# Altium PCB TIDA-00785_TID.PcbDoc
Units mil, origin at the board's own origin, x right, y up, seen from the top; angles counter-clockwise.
Board outline 1501 x 1000 mil, 2 copper layers (Top Layer, Bottom Layer), stack 62 mil thick; 48 components, 15 nets, 95 pads, 18 vias.
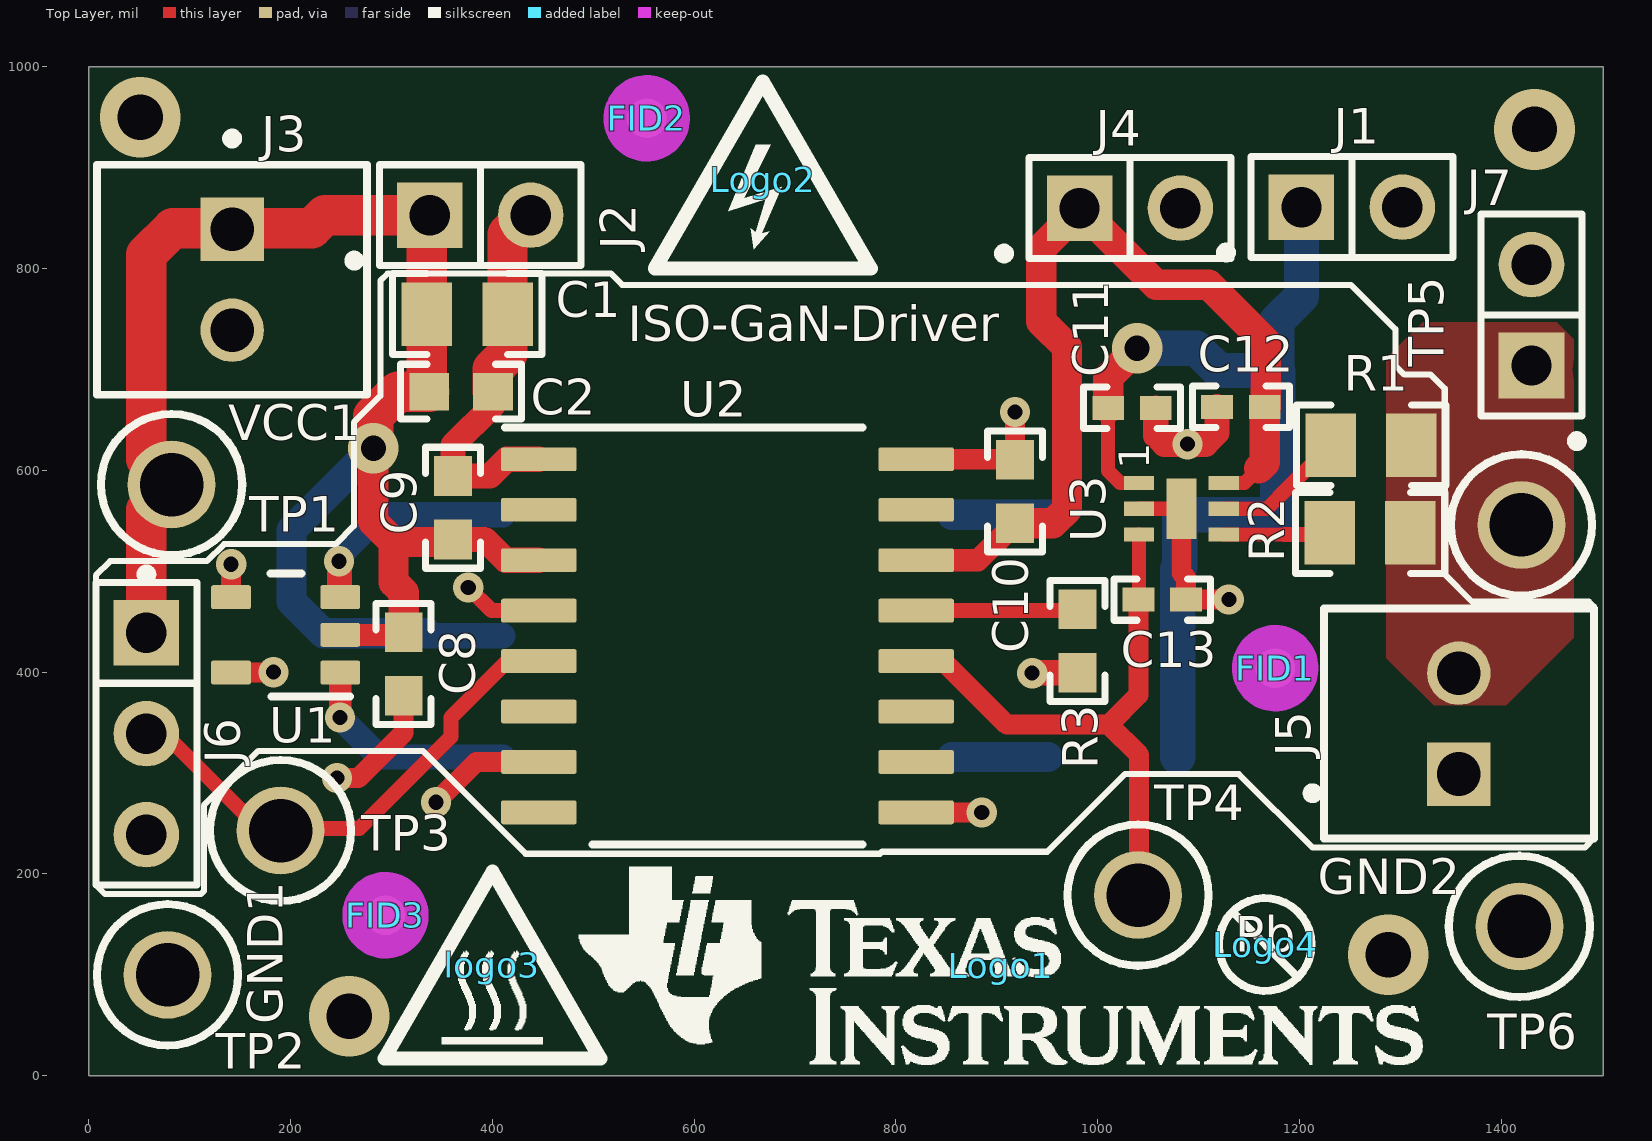
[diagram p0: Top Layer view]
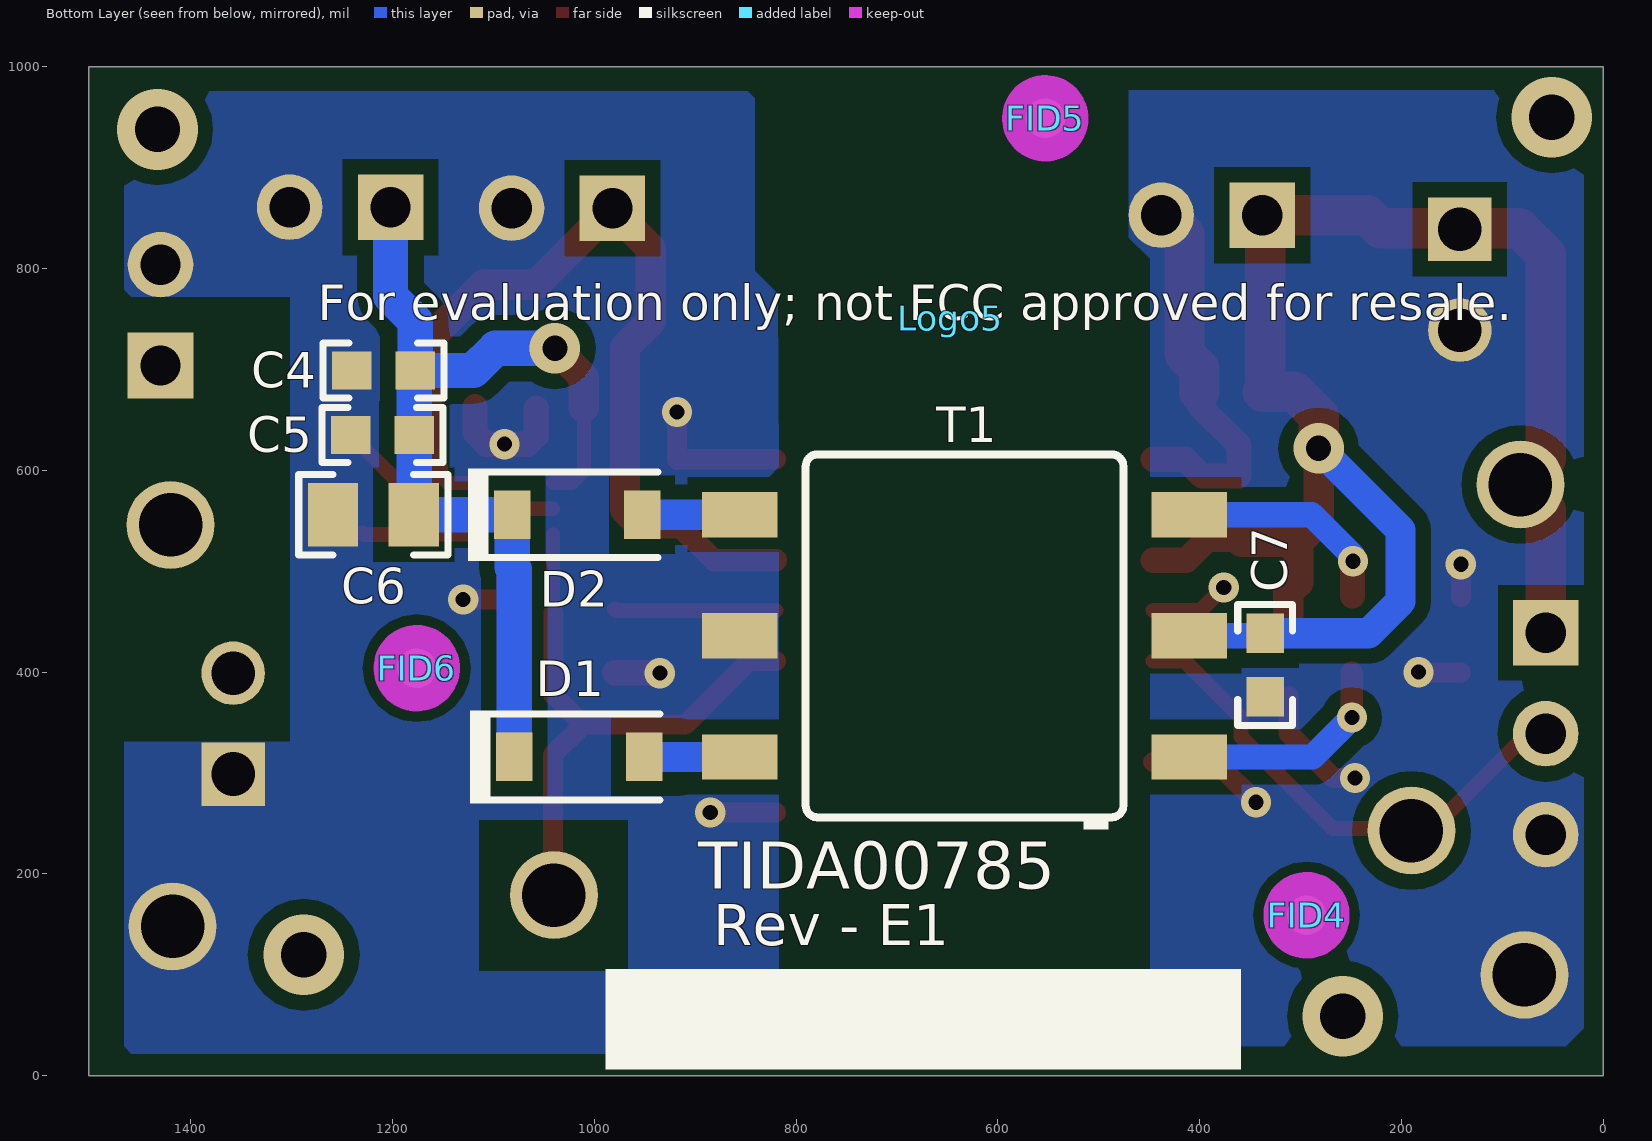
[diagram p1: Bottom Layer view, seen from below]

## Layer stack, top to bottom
Top Solder: solder mask 0.4, Solder Resist, Dk 3.5
Top Layer: signal copper 1.4
Dielectric1: core 59.2, FR-4, Dk 4.8
Bottom Layer: signal copper 1.4
Bottom Solder: solder mask 0.4, Solder Resist, Dk 3.5

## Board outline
0,0 0,1000 1501,1000 1501,0

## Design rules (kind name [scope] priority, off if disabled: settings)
AcuteAngle [All] p1: minimum=4.50000000000000E+0001 checktracksonly=FALSE
AssemblyTestPointUsage [All] p1: valid=2
Clearance Clearance_1 [All] p1: gap=10 except(8: Track-SMDPad; 9.4: SMDPad-SMDPad Track-Track; 15: Poly-Poly SMDPad-Poly Poly-Region Track-Poly Via-Poly THPad-Poly)
Clearance Clearance_Keepouts [((IsTrack Or IsArc) And Not InPoly) And IsFree and IsKeepOut vs ((IsTrack Or IsArc) And Not InPoly) And IsFree and IsKeepOut] p2: gap=0
Clearance Clearance_BoardEdge_MountingHoles [OnCopper and InComponentClass('Mounting Holes') vs IsKeepOut] p3: gap=40
Clearance Clearance_BoardEdge_Poly [OnCopper and InPoly vs IsKeepOut] p4: gap=25
Clearance Clearance_BoardEdge [OnCopper and Not InComponentClass('Logo') and not InComponentClass('FiducialMark') and not InRegion(1000,500,4000,800) and Not IsKeepout vs IsKeepOut] p5: gap=20
Clearance Clearance_Poly [All] p6: gap=100
Clearance [All] p7: gap=7.87
ComponentClearance ComponentClearance_MountingHoles_FiducialMarks [InComponentClass('Mounting Holes') vs InComponentClass('FiducialMark')] p1: gap=18 collisioncheckmode=3 verticalgap=10 showdistances=FALSE
ComponentClearance ComponentClearance_Shunt [InComponentClass('Header') vs InComponentClass('Shunt')] p2: gap=0 collisioncheckmode=3 verticalgap=0 showdistances=FALSE
ComponentClearance ComponentClearance_Logo [InComponentClass('Logo')] p3: gap=18 collisioncheckmode=3 verticalgap=10 showdistances=FALSE
ComponentClearance ComponentClearance_ScrewToNut [(HasFootprint('NY PMS 440 0025 PH')) vs (HasFootprint('Keystone_1902C'))] p4: gap=5 collisioncheckmode=3 verticalgap=10 showdistances=FALSE
ComponentClearance ComponentClearance_MountingHoles [InComponentClass('Mounting Holes')] p5: gap=18 collisioncheckmode=3 verticalgap=100000 showdistances=FALSE
ComponentClearance ComponentClearance_SmallPassives [HasFootprint('0201*') or HasFootprint('0402*') or HasFootprint('0508') or HasFootprint('0603*') or HasFootprint('0612') or HasFootprint('0805*') or HasFootprint('0815*') or HasFootprint('0830*') or HasFootprint('1206*') or HasFootprint('1210*') or HasFootprint('1808*') or HasFootprint('1812*') or HasFootprint('1825*') or HasFootprint('2010*') or HasFootprint('2220*') or HasFootprint('2225*') or HasFootprint('2512*') or HasFootprint('2728*') or HasFootprint('3518*') vs HasFootprint('0201*') or HasFootprint('0402*') or HasFootprint('0508') or HasFootprint('0603*') or HasFootprint('0612') or HasFootprint('0805*') or HasFootprint('0815*') or HasFootprint('0830*') or HasFootprint('1206*') or HasFootprint('1210*') or HasFootprint('1808*') or HasFootprint('1812*') or HasFootprint('1825*') or HasFootprint('2010*') or HasFootprint('2220*') or HasFootprint('2225*') or HasFootprint('2512*') or HasFootprint('2728*') or HasFootprint('3518*')] p6: gap=18 collisioncheckmode=3 verticalgap=10 showdistances=FALSE
ComponentClearance ComponentClearance_THtoSMT [IsThruComponent vs IsSMTComponent] p7: gap=18 collisioncheckmode=3 verticalgap=18 showdistances=FALSE
ComponentClearance ComponentClearance_THtoTH [IsThruComponent vs IsThruComponent] p8: gap=18 collisioncheckmode=3 verticalgap=18 showdistances=FALSE
ComponentClearance [All] p9: gap=16 collisioncheckmode=3 verticalgap=10 showdistances=FALSE
DiffPairsRouting [All] p1: maxlimit=100 minlimit=10 mostfreqgap=10 toplayer_minwidth=15 toplayer_maxwidth=15 toplayer_prefwidth=15 bottomlayer_minwidth=15 bottomlayer_maxwidth=15 bottomlayer_prefwidth=15 maxuncoupledlength=1000
FabricationTestPointUsage TestPointUsage [All] p1: valid=2 allowmultiple=FALSE
FabricationTestpoint Testpoint [All] p1: side=3 testpointundercomponent=TRUE minsize=40 maxsize=100 preferedsize=60 minholesize=0 maxholesize=40 preferedholesize=32 testpointgrid=1 allowsidetop=TRUE allowsidebottom=TRUE usegrid=TRUE gridtolerance=0.01
FanoutControl Fanout_LCC [IsLCC] p1: bgadir=Out bgaviamode=Centered fanoutstyle=Auto fanoutdirection=Alternating viagrid=1 // Fanout_LCC (Default Rule)
FanoutControl Fanout_BGA [IsBGA] p2: bgadir=Out bgaviamode=Centered fanoutstyle=Auto fanoutdirection=Alternating viagrid=1 // Fanout_BGA (Default Rule)
FanoutControl Fanout_Default [All] p4: bgadir=Out bgaviamode=Centered fanoutstyle=Auto fanoutdirection=Alternating viagrid=1 // Fanout_Default (Default Rule)
FanoutControl Fanout_Small [(CompPinCount < 5)] p5: bgadir=Out bgaviamode=Centered fanoutstyle=Auto fanoutdirection=OutThenIn viagrid=1 // Fanout_Small (Default Rule)
HoleSize [All] p1: absolutevalues=TRUE maxlimit=251 minlimit=8 maxpercent=80.000 minpercent=20.000
MinimumAnnularRing MinimumAnnularRing_ThermalPadVias [IsVia and InAnyComponent] p1: minimumring=5.91
MinimumAnnularRing [All] p2: minimumring=9
MinimumSolderMaskSliver MinimumSolderMaskSliver_Logo [InComponentClass('Logo') vs InComponentClass('Logo')] p1: minsoldermaskwidth=0.7
MinimumSolderMaskSliver [All] p2: minsoldermaskwidth=3.94
PlaneClearance [All] p1: clearance=50
PlaneConnect [All] p1: planeconnectstyle=Direct reliefexpansion=10 reliefentries=4 reliefconductorwidth=10 reliefairgap=10
PolygonConnect [All] p1: connectstyle=Direct reliefconductorwidth=10 reliefentries=4 polygonreliefangle="90 Angle" airgapwidth=10
RoutingVias ThermalPadVias [IsVia and InAnyComponent] p1: holewidth=7.87 width=19.68 viastyle="Through Hole" minholewidth=7.87 minwidth=19.68 maxholewidth=12.99 maxwidth=23.62
RoutingVias [All] p2: holewidth=16 width=34 viastyle="Through Hole" minholewidth=7.87 minwidth=26 maxholewidth=40 maxwidth=65
SilkToSilkClearance SilkToSilkClearance_Pb-FreeLogo [(HasFootprint('Pb-Free_Overlay_Medium') OR HasFootprint('Pb-Free_Overlay_Small')) vs (HasFootprint('Pb-Free_Overlay_Medium') OR HasFootprint('Pb-Free_Overlay_Small'))] p1: silktosilkclearance=0
SilkToSilkClearance [All] p2: silktosilkclearance=4
SilkToSolderMaskClearance "Silk to Solder Mask Opening" [IsPad] p1: minsilkscreentomaskgap=4 clearancetoexposedcopper=TRUE
SolderMaskExpansion [All] p1: expansion=1.97
UnpouredPolygon [All] p1: allowunpoured=FALSE
Width [All] p1: maxlimit=100 minlimit=6 preferedwidth=10 checkconnectedcopper=TRUE
14 further rules are at their usual default settings.

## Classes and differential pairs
component class TIDA-00785_RefD-ISO-GaN-Driver: C1 C2 C4 C5 C6 C7 C8 C9 C10 C11 C12 C13 D1 D2 J1 J2 J3 J4 J5 J6 J7 R1 R2 R3 T1 TP1 TP2 TP3 TP4 TP5 TP6 U1 U2 U3
component class Logo: Logo1
component class TIDA-00785_TID_Hardware: FID1 FID2 FID3 FID4 FID5 FID6 Logo1 Logo2 logo3 Logo4 Logo5 ZZ1 ZZ2 ZZ3
component class FiducialMark: FID1 FID2 FID3 FID4 FID5 FID6
component class AssemblyNote: ZZ1 ZZ2 ZZ3
component class Header: J1 J2 J4 J6 J7

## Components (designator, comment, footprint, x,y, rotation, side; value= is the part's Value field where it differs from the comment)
C1 "GRM21BR6YA106KE43L" 0805_HV 375,755 r0 top
C2 "GRM188R61H105KAALD" 0603 369,678 r0 top
C4 "06033C104JAT2A" 0603 1209,699 r0 bottom
C5 "GRM188R61H105KAALD" 0603 1210,635 r0 bottom
C6 "GRM21BR6YA106KE43L" 0805_HV 1219,556 r0 bottom
C7 "06033C104JAT2A" 0603 335,407 r270 bottom
C8 "GRM188R61H105KAALD" 0603 312,408 r270 top
C9 "06033C104JAT2A" 0603 361,563 r90 top
C10 "GRM188R61E105KA12D" 0603 918,579 r90 top
C11 "C1005X7R1C224K050BC" 0402 1034,662 r0 top
C12 "C1005X7R1C224K050BC" 0402 1142,663 r180 top
C13 "C0402C101J3GACTU" 0402 1064,472 r0 top
D1 "MBR0520LT1G" SOD-123 1015,316 r180 bottom
D2 "MBR0520LT1G" SOD-123 1017,556 r180 bottom
FID1 "Fiducial" Fiducial10-20 1176,404 r0 top
FID2 "Fiducial" Fiducial10-20 553,949 r0 top
FID3 "Fiducial" Fiducial10-20 294,159 r0 top
FID4 "Fiducial" Fiducial10-20 294,159 r180 bottom
FID5 "Fiducial" Fiducial10-20 553,949 r180 bottom
FID6 "Fiducial" Fiducial10-20 1176,404 r180 bottom
J1 "HTSW-102-07-G-S" Samtec_HTSW-102-07-G-S 1252,861 r0 top
J2 "HTSW-102-07-G-S" Samtec_HTSW-102-07-G-S 388,853 r0 top
J3 "282834-2" TEC_282834-2 142,789 r270 top
J4 "HTSW-102-07-G-S" Samtec_HTSW-102-07-G-S 1032,860 r0 top
J5 "282834-2" TEC_282834-2 1358,349 r90 top
J6 "HTSW-103-07-G-S" Samtec_HTSW-103-07-G-S 57,339 r270 top
J7 "HTSW-102-07-G-S" Samtec_HTSW-102-07-G-S 1430,754 r90 top
Logo1 "Texas Instruments" TI_Stacked_Overlay_Small 904,109 r0 top
Logo2 "DANGER HIGH VOLTAGE" IEC_HighVoltage_Small 668,888 r0 top
logo3 "CAUTION HOT SURFACE" IEC_HotSurface_Small 400,110 r0 top
Logo4 "Pb-Free Symbol" Pb-Free_Overlay_Small 1166,130 r0 top (schematic designator Logo2)
Logo5 "FCC disclaimer" FCC_disclaimer 647,751 r180 bottom
R1 "CRCW080510R0FKEA" 0805_HV 1271,625 r0 top
R2 "CRCW08051R00FKEA" 0805_HV 1270,538 r0 top
R3 "CRCW06030000Z0EA" 0603 980,431 r90 top
T1 "750313638" Wurth_750313638 633,436 r0 bottom
TP1 "5005" Keystone5005 82,586 r180 top
TP2 "5006" Keystone5006 78,100 r0 top
TP3 "5122" Keystone5122#1 197,243 r90 top
TP4 "5122" Keystone5122#2 1040,179 r90 top
TP5 "5122" Keystone5122#2 1420,546 r90 top
TP6 "5006" Keystone5006 1418,148 r90 top
U1 "SN6501DBVR" DBV0005A_N 195,437 r180 top
U2 "ISO7821FDWR" DW0016B_N 633,436 r0 top
U3 "UCC27611DRV" DRV 1083,562 r270 top
ZZ1 "These assemblies are ESD sensitive, ESD precautions shall be observed." AssemblyNote -14,3586.11 r0 top
ZZ2 "These assemblies must be clean and free from flux and all contaminants. Use of no clean flux is not acceptable." AssemblyNote -14,3497.56 r0 top
ZZ3 "These assemblies must comply with workmanship standards IPC-A-610 Class 2, unless otherwise specified." AssemblyNote -14,3409 r0 top

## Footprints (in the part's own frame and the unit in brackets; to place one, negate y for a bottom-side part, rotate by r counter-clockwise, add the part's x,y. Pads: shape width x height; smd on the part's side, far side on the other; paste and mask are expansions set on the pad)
0402 [mm] "0402 from SM-752 data"
  rect 0.8x0.6 smd: 1(-0.6,0) 2(0.6,0)
  silkscreen extent -1.22,-0.52 1.22,0.52, body extent -0.55,-0.3 0.55,0.3, height 0.6
0603 [mm] "0603 from SM-752 data"
  rect 1x0.95 smd: 1(-0.8,0) 2(0.8,0)
  silkscreen extent -1.52,-0.69 1.52,0.69, body extent -0.87,-0.47 0.87,0.47, height 1
0805_HV [mil] "0805 with 30mil clearance between pads"
  rect 50x63 smd: 1(-40,0) 2(40,0)
  silkscreen extent -74,-40 74,40, body extent -43,-29 43,29, height 57
AssemblyNote [mil] "Assembly Note"
DBV0005A_N [mm] "SOT23, 5-Leads, Body 2.9x1.6mm, Pitch 0.95mm, Lead Span 2.8mm, IPC Medium Density"
  rrect17% 1x0.6 smd: 1(-1.375,0.95) 2(-1.375,0) 3(-1.375,-0.95) 4(1.375,-0.95) 5(1.375,0.95)
  silkscreen extent -1.63,-1.55 0.38,1.55, body extent -1.42,-1.46 1.42,1.46, height 1.09
DRV [mil]
  rect 14x30 smd mask+1.18: 1(-25.6,-42) 2(0,-42) 3(25.6,-42) 4(25.6,42) 5(0,42) 6(-25.6,42)
  rect 60x30 smd mask+1.15: 7(0,0)
DW0016B_N [mm] "SOIC, 16-Leads, Body 10.5x7.6mm, Pitch 1.27mm, IPC Medium Density"
  rrect17% 1.9x0.6 smd: 1(-4.75,4.445) 2(-4.75,3.175) 3(-4.75,1.905) 4(-4.75,0.635) 5(-4.75,-0.635) 6(-4.75,-1.905) 7(-4.75,-3.175) 8(-4.75,-4.445) 9(4.75,-4.445) 10(4.75,-3.175) 11(4.75,-1.905) 12(4.75,-0.635) 13(4.75,0.635) 14(4.75,1.905) 15(4.75,3.175) 16(4.75,4.445)
  silkscreen extent -5.6,-5.25 3.4,5.25, body extent -5.17,-5.15 5.17,5.15, height 2.59
FCC_disclaimer [mil]
Fiducial10-20 [mm]
  round 1 smd mask+0.5: 1(0,0)
  Top Layer keep-out circle w1.178: c0,0 r0.5
IEC_HighVoltage_Small [mil]
  silkscreen extent -107,-88 107,97
IEC_HotSurface_Small [mil]
  silkscreen extent -107,-93 107,92
Keystone5005 [mil] "Keystone Compact loops"
  round 87 hole 63: 1(0,0)
  silkscreen extent -70,-70 70,70, body extent -63,-63 62,63, height 225
Keystone5006 [mil] "Keystone Compact loops"
  round 87 hole 63: 1(0,0)
  silkscreen extent -70,-70 70,70, body extent -63,-63 62,63, height 225
Keystone5122#1 [mil] "Keystone Compact loops"
  round 87 hole 63: 1(0,7)
  silkscreen extent -70,-63 70,77, body extent -63,-56 62,70, height 225
Keystone5122#2 [mil] "Keystone Compact loops"
  round 87 hole 63: 1(0,0)
  silkscreen extent -70,-70 70,70, body extent -63,-63 62,63, height 225
Pb-Free_Overlay_Small [mil]
  silkscreen extent -46,-46 46,46
Samtec_HTSW-102-07-G-S [mm] "Samtec 100mil, 1x2, 230 mil above insulator"
  rect 1.65x1.65 hole 1.016 mask+0: 1(-1.27,0)
  round 1.65 hole 1.016 mask+0: 2(1.27,0)
  silkscreen extent -3.3,-1.27 2.54,1.27, body extent -2.54,-1.27 2.54,1.27, height 8.38
Samtec_HTSW-103-07-G-S [mm] "Samtec 100mil, 1x3, 230 mil above insulator"
  rect 1.65x1.65 hole 1.016 mask+0: 1(-2.54,0)
  round 1.65 hole 1.016 mask+0: 2(0,0) 3(2.54,0)
  silkscreen extent -4.14,-1.27 3.81,1.27, body extent -3.81,-1.27 3.81,1.27, height 8.38
SOD-123 [mm] "On Semi recommended land pattern"
  rect 0.915x1.22 smd: 1(-1.637,0) 2(1.637,0)
  silkscreen extent -2.74,-1.17 2.03,1.17, body extent -1.93,-0.9 1.93,0.9, height 1.35
TEC_282834-2 [mm] "TEC"
  rect 1.6x1.6 hole 1.1: 1(-1.27,0)
  round 1.6 hole 1.1: 2(1.27,0)
  silkscreen extent -3.66,-3.4 2.9,3.4, body extent -2.77,-3.25 2.77,3.25, height 10.01
TI_Stacked_Overlay_Small [mil]
  silkscreen extent -418,-98 418,98
Wurth_750313638 [mm] "SMD, 6-Leads, Body 8x9.14mm, Pitch 3.05mm"
  rect 1.9x1.14 smd: 1(-5.655,3.05) 2(-5.655,0) 3(-5.655,-3.05) 4(5.655,-3.05) 5(5.655,0) 6(5.655,3.05)
  silkscreen extent -4,-4.57 4,4.87, body extent -6.35,-4.57 6.35,4.57, height 7.62

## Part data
C1 C6: "CAP, CERM, 10 µF, 35 V, +/- 10%, X5R, 0805"
C2 C5 C8: "CAP, CERM, 1 µF, 50 V, +/- 10%, X5R, 0603"
C4 C7 C9: "CAP, CERM, 0.1 µF, 25 V, +/- 5%, X7R, 0603"
C10: "CAP, CERM, 1 µF, 25 V, +/- 10%, X5R, 0603"
C11 C12: "CAP, CERM, 0.22 µF, 16 V, +/- 10%, X7R, 0402"
C13: "CAP, CERM, 100 pF, 25 V, +/- 5%, C0G/NP0, 0402"
D1 D2: "Diode, Schottky, 20 V, 0.5 A, SOD-123"
FID1 FID2 FID3 FID4 FID5 FID6: "Fiducial mark.  There is nothing to buy or mount."
J1 J2 J4 J7: "Header, 100mil, 2x1, Gold, TH"
J3 J5: "Terminal Block, 2x1, 2.54mm, TH"
J6: "Header, 100mil, 3x1, Gold, TH"
Logo1: library part TI_Logo, "Texas Instrument Corporate Signature"
Logo2: library part IEC_HighVoltage, "IEC 61010-1 High Voltage Warning"
logo3: library part IEC_HotSurface, "IEC 61010-1 Hot Surface Warning"
Logo4: library part Pb-Free
Logo5: library part FCC_disclaimer, "FCC_disclaimer"
R1: "RES, 10.0, 1%, 0.125 W, 0805"
R2: "RES, 1.00, 1%, 0.125 W, 0805"
R3: "RES, 0, 5%, 0.1 W, 0603"
T1: "Transformer, 340 uH, SMT"
TP1: "Test Point, Compact, Red, TH"
TP2 TP6: "Test Point, Compact, Black, TH"
TP3 TP4 TP5: "Test Point, Compact, Blue, TH"
U1: "Transformer Driver for Isolated Power Supplies, DBV0005A"
U2: "High-Performance, 8000 VPK Reinforced Dual Channel Digital Isolator, DW0016B"
U3: "IC, 4A/8A Single Channel High-Speed Low-Side Gate Drivers"
ZZ1 ZZ2 ZZ3: library part AssemblyNote

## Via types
v1: diameter 30, hole 15, Top Layer to Bottom Layer, 12 vias
v2: diameter 80, hole 45, Top Layer to Bottom Layer, 4 vias
v3: diameter 50, hole 25, Top Layer to Bottom Layer, 2 vias

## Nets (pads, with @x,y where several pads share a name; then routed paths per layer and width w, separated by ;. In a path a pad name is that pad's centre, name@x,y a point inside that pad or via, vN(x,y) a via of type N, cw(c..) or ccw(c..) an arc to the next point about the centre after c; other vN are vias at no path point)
GND1: C1.2 C2.2 C7.2 C8.2 C9.2 J2.2 J3.2 J6.3 TP2.1 U1.4 U1.5 U2.1 U2.7 | length 695.2
  Top Layer w20: U1.5 182.6,399.6 v1(183,400) ; U1.4 140.87,506.87 v1(141,507) ; v1(246,295) 267,295 312,340 C8.2 ; v1(344,271) 384,311 U2.7
  Top Layer w25: C2.2 400.5,664.5 361,625 C9.2 397.5,594.5 414,611 U2.1
  Top Layer w40: C2.2 400.5,700.5 415,715 C1.2 415,834 J2.2@434,853
GND2: C4.2 C5.2 C6.2 C10.2 C11.2 C12.2 C13.2 J1.2 J4.2 J5.1 J7.2 R3.1 T1.5 TP6.1 U2.9 U2.16 U3.2 U3.7 | length 554.4
  Top Layer w14: U3.2 U3.7
  Top Layer w20: U2.9 v1(885,261) ; U2.16 917.5,611 C10.2 v1(918,658) ; U3.7 1083,498.5 1087.62,493.88 C13.2 v1(1130,472)
  Top Layer w25: v1(935,399) 935.5,399.5 R3.1 ; C11.2 1057.62,634.38 1066,626 v1(1089,626) 1107,626 1118.38,637.38 C12.2
NetC13_1: C13.1 TP4.1 U2.12 U3.3 | length 599.8
  Top Layer w14: 1040.38,459 1041,459.62 U3.3
  Top Layer w20: U2.12 847,411 910,348 1011,348 ; TP4.1 1041,180 1041,318 1011,348 ; 1040.38,459 1040.38,377.38 1011,348
NetD1_2: D1.2 T1.6 | length 94.9
  Bottom Layer w25: D1.2@950.45,315.92 D1.2
  Bottom Layer w30: T1.6 D1.2@950.45,315.92
NetD2_2: D2.2 T1.4 | length 96.9
  Bottom Layer w15: D2.2@952.45,556.08 D2.2
  Bottom Layer w30: T1.4 D2.2@952.45,556.08
NetJ5_2: J5.2 J7.1 R1.2 R2.2 TP5.1
NetJ6_2: J6.2 TP3.1 U2.5 | length 493.9
  Top Layer w15: J6.2@75,339 162,252 162,245 268,245 359,336 359,355 415,411 U2.5
NetR1_1: R1.1 U3.5 | length 132.1
  Top Layer w14: U3.5 1168,562 1180,574
  Top Layer w15: 1180,574 R1.1
NetR2_1: R2.1 U3.4 | length 105.7
  Top Layer w14: U3.4 1185,536.4
  Top Layer w15: 1185,536.4 1228.4,536.4 R2.1
NetR3_2: R3.2 U2.13 | length 160.6
  Top Layer w15: U2.13 978.5,461 R3.2
NetT1_1: T1.1 U1.1 | length 222.2
  Top Layer w20: v1(249,355) v1@249.13,355.13
  Top Layer w22: v1@249.13,355.13 U1.1
  Bottom Layer w25: v1(249,355) 288.08,315.92 T1.1
NetT1_3: T1.3 U1.3 | length 219.1
  Top Layer w25: v1(248,510) 248.4,509.6 U1.3@248.4,475.4
  Bottom Layer w25: v1(248,510) 248,515 289.08,556.08 T1.3
VCC1: C1.1 C2.1 C7.1 C8.1 C9.1 J2.1 J3.1 J6.1 T1.2 TP1.1 U1.2 U2.3 | length 1784.3
  Top Layer w20: C9.1@358.5,529 C9.1
  Top Layer w22: U1.2 309.5,437 C8.1
  Top Layer w25: C9.1 392.5,531.5 413,511 U2.3
  Top Layer w30: v3(282,622) 282,549 302,529 ; C8.1 312,479 302,489 302,529 ; C9.1@358.5,529 302,529
  Top Layer w40: J6.1 57,561 TP1.1 57,611 57,814 83,840 221,840 234,853 334,853 335,852 C1.1 335,680.5 C2.1 306,678 282,654 v3(282,622)
  Bottom Layer w25: C7.1 337.5,436 T1.2
  Bottom Layer w30: v3(282,622) 200.75,540.75 200.75,470.25 232.5,438.5 C7.1
VCC2: C4.1 C5.1 C6.1 C11.1 D1.1 D2.1 J1.1 U3.1 | length 970.6
  Top Layer w14: C11.1 1010.38,599.62 1022.4,587.6 U3.1
  Top Layer w30: C11.1 1010.38,692.38 v3(1039,721)
  Bottom Layer w30: 1157,699 C4.1
  Bottom Layer w35: v3(1039,721) 1098,721 1120,699 1157,699 ; D1.1 1079.47,502 1081.47,504 D2.1 C6.1 1178.5,556.5 C5.1 1178.5,698 C4.1 1177.5,748 1202,772.5 J1.1
VREF: C10.1 C12.1 J4.1 U2.14 U3.6 | length 904.5
  Top Layer w14: U3.6 1145.6,587.6 1160,602
  Top Layer w22: U2.14 881.5,511 C10.1
  Top Layer w30: C10.1 955.5,547.5 969.63,561.63 969.63,722 944,747.63 944,820 982,858 J4.1 1058,784 1110,784 1166.62,727.38 C12.1@1166.62,662 ; 1160,602 1165.62,607.62 C12.1
pads on no net: FID1.1 FID2.1 FID3.1 FID4.1 FID5.1 FID6.1 U2.2 U2.4 U2.6 U2.8 U2.10 U2.11 U2.15
copper on no net: | length 79.5
  Top Layer w15: v1(376,484) 399,461 445.99,461
  other v2: 258,59 1288,120 1433,938 51,950

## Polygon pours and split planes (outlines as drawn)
NetJ5_2 on Top Layer "Top Layer-No Net" (solid, remove dead copper, pour order 8): 1400,747 1323,747 1322,747 1293,718 1286,711 1286,667 1286,414 1333,367 1403,367 1405,367 1472,434 1472,730 1455,747
GND2 on Bottom Layer "Bottom Layer-No Net" (solid, remove dead copper, pour order 9): 841,976 841,798 818.06,775.06 817,594 817,23 818,22 1189,22 1230,22 1466,22 1466,976
GND1 on Bottom Layer "Bottom Layer-No Net" (solid, remove dead copper, pour order 13): 19,47 37,29 408,29 449,29 449,422 449,616.02 449,809.86 470,830.86 470,977.02 246,977.02 141,977.02 88,977.02 56,977.02 19,977.02

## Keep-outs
Keep-Out Layer:
  lines w10: -204,3207 cw(c-199,3207) -199,3212 ccw(c-199,3207) -204,3207
  text ".Layer_Name" at 378,-1101.49 h60

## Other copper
Top Layer:
  text ".Layer_Name" at 378,-1101.49 h60
Bottom Layer:
  pour cut-out: 1301.55,331 1301.55,538 1301.55,632 1301.55,772 1478,772 1478,757 1478,331
  pour cut-out: 967,253 967,104 1114,104 1114,253
  text ".Layer_Name" at 378,-1101.49 h60

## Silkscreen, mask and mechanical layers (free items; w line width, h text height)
Top Overlay:
  lines w6: 7,189 7,496 21,510 117,510 134,527 244.64,527 262.63,544.99 262.63,647.63 289,674 289,788 296,795 517.64,795 528.64,784 1251,784 1295,740 1295,704 1304,695 1330,695 1344,681 1344,497 1371,470 1487,470 1492,465 1492,235.17 1482.83,226 1213,226 1140,299 1027,299 950,222 786,222 784,220 611,220 433,220 331,322 176,322 168,322 114,268 114,183 111,180 16,180 7,189
  text "ISO-GaN-Driver" at 534,716 h60
  text "VCC1" at 138,630 h35
  text "GND2" at 1218,180 h35
  text "GND1" at 192,51 h35 r90
  text ".Layer_Name" at 378,-1101.49 h60
Bottom Overlay:
  rectangle: 359,6 989,106
  text "TIDA00785" at 897,170 h80
  text "Rev - E1" at 882,116 h70
  text ".Layer_Name" at 378,-1101.49 h60
Top Paste:
  text ".Layer_Name" at 378,-1101.49 h60
Bottom Paste:
  text ".Layer_Name" at 378,-1101.49 h60
Top Solder:
  text ".Layer_Name" at 378,-1101.49 h60
  text ".Layer_Name" at 378,-1101.49 h60
Bottom Solder:
  text ".Layer_Name" at 378,-1101.49 h60
Drill Guide:
  text ".Layer_Name" at 378,-1101.49 h60
M1 Board Outline:
  lines w6: 0,0 1501,0 1501,264 1501,563 1501,1000 0,1000 0,0
  text ".Layer_Name" at 378,-1101.49 h60
M2 Board Dimensions:
  rectangle: -74,-643 301,-518
  rectangle: -199,-518 -74,-393
  lines w7: -199,-518 801,-518 ; -74,-643 -74,-393 ; 51,-643 51,-393 ; 301,-643 301,-393 ; 551,-643 551,-393 ; -199,-643 801,-643 801,-393 -199,-393 -199,-643
M3 3D STEP Top:
  text ".Layer_Name" at 378,-1101.49 h60
M4 3D STEP Bottom:
  text ".Layer_Name" at 378,-1101.49 h60
M5 Assembly Top:
  lines w10: -491,-1173.17 6109,-1173.17 ; -491,-969.83 6111,-969.83 ; -491,-766.5 -491,-1376.5 3514,-1376.5 6111,-1376.5 6111,-766.5 -490.5,-766.5 -490.5,-1376.5 1085,-1376.5 ; 1974,-1376.5 1974,-766.5 ; 3241,-969.83 3241,-766.5 ; 4081,-969.83 4081,-766.5 ; 4703,-1383 4703,-1180.17
  text "COMPONENTS MARKED 'DNP' SHOULD NOT BE POPULATED." at 954.5,-561.5 h60
  text "ASSEMBLY VARIANT:" at 954,-677 h60
  text ".VariantName" at 1990,-677 h60
  text "PCB VIEWED FROM TOP SIDE" at -427.5,-898.67 h60
  text "BOARD #:" at 2049,-898.67 h60
  text ".PRJ_Number" at 2594.5,-898.67 h60
  text "REV:" at 3439,-898.67 h60
  text ".PCB_Rev" at 3730.5,-898.67 h60
  text "SVN REV:" at 4277,-898.67 h60
  text ".VersionControl_RevNumber" at 4783,-898.67 h60
  text "TID #:" at 2049,-1102 h60
  text ".TID" at 2594.5,-1102 h60
  text "PLOT NAME =" at -427.5,-1307.34 h60
  text ".plot_File_Name" at 378,-1307.34 h60
  text "GENERATED    :" at 2051,-1307.34 h60
  text ".Print_Date" at 2920.5,-1307.34 h60
  text ".Print_Time" at 3649.5,-1307.34 h60
  text "TEXAS INSTRUMENTS" at 4914,-1307.34 h60
M6 Assembly Bottom:
  lines w10: -491.5,-970.33 6110.5,-970.33 ; -489.5,-1173.67 6110.5,-1173.67 ; 916.5,-1383.5 916.5,-1180.67 ; 1538.5,-970.33 1538.5,-767 ; 2378.5,-970.33 2378.5,-767 ; 3645.5,-1377 3645.5,-767 ; 4534.5,-1377 6110,-1377 6110,-767 -491.5,-767 -491.5,-1377 2105.5,-1377 6110.5,-1377 6110.5,-767
  text "COMPONENTS MARKED 'DNP' SHOULD NOT BE POPULATED." at 5903,-561 h60
  text ".VariantName" at 4859,-677 h60
  text "ASSEMBLY VARIANT:" at 5898,-677 h60
  text ".VersionControl_RevNumber" at 836.5,-899.17 h60
  text "SVN REV:" at 1342.5,-899.17 h60
  text ".PCB_Rev" at 1889,-899.17 h60
  text "REV:" at 2180.5,-899.17 h60
  text ".PRJ_Number" at 3025,-899.17 h60
  text "BOARD #:" at 3570.5,-899.17 h60
  text "PCB VIEWED FROM BOTTOM SIDE" at 6047,-899.17 h60
  text ".TID" at 3025,-1102.5 h60
  text "TID #:" at 3570.5,-1102.5 h60
  text "TEXAS INSTRUMENTS" at 705.5,-1307.84 h60
  text ".Print_Time" at 1970,-1307.84 h60
  text ".Print_Date" at 2699,-1307.84 h60
  text "GENERATED    :" at 3568.5,-1307.84 h60
  text ".plot_File_Name" at 5241.5,-1307.84 h60
  text "PLOT NAME =" at 6047,-1307.84 h60
M9 Title Sheet:
  drawing of 57 lines, arcs and shapes, not listed
  text "1" at 540.84,7793.5 h70
  text "2" at 3036.5,7793.5 h70
  text "3" at 5525.84,7793.5 h70
  text "4" at 8032.51,7793.5 h70
  text "5" at 10531.5,7793.5 h70
  text "6" at 13036.5,7793.5 h70
  text "A" at -615.5,6650.5 h70
  text "A" at 14184.5,6650.5 h70
  text "B" at -615.5,4270.5 h70
  text "B" at 14184.5,4270.5 h70
  text "C" at -615.5,1895.5 h70
  text "C" at 14184.5,1895.5 h70
  text "PROJECT TITLE:" at 11144.5,34.5 h45
  text "ISO-GaN-Driver" at 11194.5,-98.83 h70
  text "DESIGNED FOR:" at 11144.5,-266.5 h45
  text "Texas Instruments" at 11194.5,-406.5 h70
  text "D" at -615.5,-474.5 h70
  text "D" at 14184.5,-474.5 h70
  text "FILE NAME:" at 11144.5,-566.5 h45
  text "ISO-GaN-Driver" at 11194.5,-686.5 h70
  text "Texas Instruments (TI) and/or its licensors do not warrant the accuracy or completeness of this specification" at 6175,-848.34 h45
  text "ENGINEER:" at 11144.5,-856.5 h45
  text "LAYOUT BY:" at 12649.5,-856.5 h45
  text "or any information contained therein. TI and/or its licensors do not warrant that this design will meet" at 6130.01,-961 h45
  text "Neeraj B" at 11194.5,-1011.49 h70
  text "Tessolve Semiconductor" at 12700,-1011.49 h70
  text "the specifications, will be suitable for your application or fit for any particular purpose, or will operate in" at 6130.01,-1073.67 h45
  text "ALTIUM DESIGNER VERSION:" at 12649.5,-1166.5 h45
  text "an implementation. TI and/or its licensors do not warrant that the design is production worthy. You should" at 6130.01,-1186.33 h45
  text "completely validate and test your design implementation to confirm the system functionality for your application." at 6175,-1299 h45
  text ".print_Scale" at 11194.5,-1299.83 h70
  text ".Application_BuildNumber" at 12700,-1299.83 h70
  text "1" at 540.84,-1506.5 h70
  text "2" at 3036.5,-1506.5 h70
  text "3" at 5525.84,-1506.5 h70
  text "4" at 8032.51,-1506.5 h70
  text "5" at 10531.5,-1506.5 h70
  text "6" at 13036.5,-1506.5 h70
M10 Fab Notes:
  drawing of 185 lines, arcs and shapes, not listed
  text "DESIGN INFORMATION" at 12182.02,5667 h60
  text "MIN. TRACK WIDTH:" at 11537.46,5487 h60
  text "6" at 12633.7,5487 h60
  text "MIL" at 12788.46,5487 h60
  text "MIN. CLEARANCE:" at 11537.46,5355 h60
  text "0.2" at 12573.7,5355 h60
  text "mm" at 12788.46,5355 h60
  text "MIN. VIA PAD SIZE:" at 11537.46,5223 h60
  text "30" at 12603.71,5223 h60
  text "MIL" at 12788.46,5223 h60
  text "0.19mm (7.5MIL)" at 12232.46,5081.29 h60
  text "MINIMUM ANNULAR RING" at 11208.23,5077 h60
  text "EXTERNAL" at 12940.46,5077 h60
  text "PER" at 11408.23,4959 h60
  text "IPC-D-275 CLASS 2 LEVEL C" at 11628.23,4959 h60
  text "MIL, HOLES" at 13116.46,4846.71 h60
  text "+/-" at 12724,4846 h60
  text "+/-" at 13578,4846 h60
  text "REGISTRATION TOLERANCES:" at 11208.23,4841 h60
  text "METAL" at 12408,4841 h60
  text "5" at 12984.2,4841 h60
  text "3" at 13817.2,4841 h60
  text "MIL" at 13933.46,4841 h60
  text "MATERIAL:" at 11133.46,4631.54 h60
  text "FR-4 High Tg" at 12119.9,4491.21 h60
  text "FR-408" at 11554.46,4482.64 h60
  text "X" at 11966.46,4482.64 h60
  text "OTHER" at 13042.46,4482.64 h60
  text "62 MIL (1.6mm) +/-10%" at 11874.56,4319.92 h60
  text "THICKNESS:" at 11208.23,4315.64 h60
  text "X" at 11746.4,4315.64 h60
  text "OTHER" at 13159.46,4315.64 h60
  text "TOLERANCE:" at 11208.23,4157.64 h60
  text "X" at 12047.53,4157.64 h60
  text "ANSI IPC-6012 TYPE 3 CLASS 2" at 12234.48,4157.64 h60
  text "OTHER +/-" at 12234.46,4001.64 h60
  text "BOW & TWIST:" at 11208.23,3844.64 h60
  text "X" at 12047.53,3844.64 h60
  text "ANSI IPC-6012 TYPE 3 CLASS 2" at 12234.48,3844.64 h60
  text "OTHER +/-" at 12234.46,3686.13 h60
  text "DRILLING:" at 11133.46,3547.64 h60
  text "REFERENCE:" at 11208.23,3430.64 h60
  text "X" at 11856.46,3430.64 h60
  text "AS SHOWN" at 12043.46,3430.64 h60
  text "X" at 12757.46,3430.64 h60
  text "NC_DRILL FILES" at 12894.46,3430.64 h60
  text "PTH MIN COPPER THICKNESS:" at 11208.23,3272.64 h60
  text "X" at 12558.46,3272.64 h60
  text "1MIL" at 12695.46,3272.64 h60
  text "OTHER" at 13192.46,3272.64 h60
  text "BOARD FINISH:" at 11133.46,3113.64 h60
  text "SILKSCREEN:" at 11288.68,2995.64 h60
  text "X" at 12237.46,2995.64 h60
  text "TOP" at 12363.46,2995.64 h60
  text "X" at 12747.46,2995.64 h60
  text "BOTTOM" at 12874.46,2995.64 h60
  text "SILKSCREEN COLOR:" at 11288.68,2828.64 h60
  text "X" at 12236.42,2828.64 h60
  text "WHITE" at 12363.46,2828.64 h60
  text "OTHER" at 12874.46,2828.64 h60
  text "SOLDER RESIST COLOR:" at 11288.68,2658.64 h60
  text "X" at 11856.42,2499.44 h60
  text "GREEN" at 11983.46,2499.44 h60
  text "BLUE" at 12574.46,2499.44 h60
  text "OTHER" at 13112.46,2499.44 h60
  text "IMMERSION GOLD (ENIG)" at 12194.46,2310.92 h60
  text "ENEPIG" at 13532,2307.64 h60
  text "SURFACE FINISH:" at 11133.46,2306.64 h60
  text "IMM. TIN/SILVER OR EQUIV" at 11463,2149.64 h60
  text "OTHER" at 12894.46,2149.64 h60
  text "X" at 11291,2147 h60
  text "ARRAY/PANEL:" at 11133.46,1970.64 h60
  text "CUT AND TRIM PER MECH LAYER 1" at 12194.46,1966.35 h60
  text "N.C. ROUTE" at 12194.46,1814.64 h60
  text "X" at 12873.46,1814.64 h60
  text "V. SCORE" at 13060.46,1814.64 h60
  text "CERTIFICATION:" at 11133.46,1677.64 h60
  text "MATERIALS AND WORKMANSHIP FOR ALL PCBS" at 11858.46,1677.64 h60
  text "TO MEET OR EXCEED THE REQUIREMENTS OF:" at 11858.46,1579.64 h60
  text "X" at 11484.96,1443.13 h60
  text "ANSI IPC-A-600F CLASS ->" at 11623.96,1443.13 h60
  text "X" at 13263.02,1443.13 h60
  text "2" at 13381.96,1443.14 h60
  text "1" at 13066.96,1441.64 h60
  text "3" at 13735.96,1441.64 h60
  text "X" at 11487.02,1283.64 h60
  text "UL 94V-0" at 11623.96,1283.64 h60
  text "X" at 12299.02,1283.64 h60
  text "RoHS" at 12435.96,1283.64 h60
  text "OTHER" at 13080.36,1283.64 h60
  text "PER ORDER" at 13477.42,1283.64 h60
  text "ADDITIONAL REQUIREMENTS:" at 11133.46,1142.64 h60
  text "MICROSECTION:" at 11208.23,1027.64 h60
  text "YES" at 12113.96,1027.64 h60
  text "REQUIRED" at 12975.46,871.49 h60
  text "BARE BOARD ELEC. TEST:" at 11208.23,868.64 h60
  text "NONE" at 12513.96,868.64 h60
  text "X" at 12848.46,868.64 h60
  text "PER ORDER" at 13567.46,868.64 h60
  text "MANUFACTURER'S UL:" at 11208.23,711.64 h60
  text "RAIL" at 12373.96,707.35 h60
  text "METAL" at 12865.77,707.35 h60
  text "X" at 13241,707 h60
  text "SILK" at 13377.46,707.35 h60
M11 Gerber Information:
  lines w10: -491,-1173.17 6109,-1173.17 ; -491,-969.83 6111,-969.83 ; -491,-766.5 -491,-1376.5 3514,-1376.5 6111,-1376.5 6111,-766.5 -490.5,-766.5 -490.5,-1376.5 1085,-1376.5 ; 1974,-1376.5 1974,-766.5 ; 3241,-969.83 3241,-766.5 ; 4081,-969.83 4081,-766.5 ; 4703,-1383 4703,-1180.17
  text "ALL ARTWORK VIEWED FROM TOP SIDE" at -427.5,-898.67 h60
  text "REV:" at 3439,-898.67 h60
  text ".PCB_Rev" at 3730.5,-898.67 h60
  text "SVN REV:" at 4277,-898.67 h60
  text ".VersionControl_RevNumber" at 4783,-898.67 h60
  text "BOARD #:" at 1988,-912 h60
  text "ISO-GaN-Driver" at 2425.86,-920 h60
  text "LAYER NAME =" at -427.5,-1101.49 h60
  text "TID #:" at 2049,-1102 h60
  text ".TID" at 2594.5,-1102 h60
  text "PLOT NAME =" at -427.5,-1307.34 h60
  text ".plot_File_Name" at 378,-1307.34 h60
  text "GENERATED    :" at 2051,-1307.34 h60
  text ".Print_Date" at 2920.5,-1307.34 h60
  text ".Print_Time" at 3649.5,-1307.34 h60
  text "TEXAS INSTRUMENTS" at 4914,-1307.34 h60
M12 Stackup:
  drawing of 191 lines, arcs and shapes, not listed
  text "Layer" at 9511.58,7377 h60
  text "Name" at 9921.49,7377 h60
  text "Material" at 10851.23,7377 h60
  text "Thickness" at 11711,7377 h60
  text "Constant" at 12360.84,7377 h60
  text "Board Layer Stack" at 12930.7,7377 h60
  text "1" at 9511.58,7257 h60
  text "Top Overlay" at 9921.49,7257 h60
  text "2" at 9511.58,7137 h60
  text "Top Solder" at 9921.49,7137 h60
  text "Solder Resist" at 10851.23,7137 h60
  text "0.40mil" at 11711,7137 h60
  text "3.5" at 12360.84,7137 h60
  text "3" at 9511.58,7017 h60
  text "Top Layer" at 9921.49,7017 h60
  text "Copper" at 10851.23,7017 h60
  text "1.40mil" at 11711,7017 h60
  text "4" at 9511.58,6897 h60
  text "Dielectric1" at 9921.49,6897 h60
  text "FR-4" at 10851.23,6897 h60
  text "59.20mil" at 11711,6897 h60
  text "4.8" at 12360.84,6897 h60
  text "5" at 9511.58,6777 h60
  text "Bottom Layer" at 9921.49,6777 h60
  text "Copper" at 10851.23,6777 h60
  text "1.40mil" at 11711,6777 h60
  text "6" at 9511.58,6657 h60
  text "Bottom Solder" at 9921.49,6657 h60
  text "Solder Resist" at 10851.23,6657 h60
  text "0.40mil" at 11711,6657 h60
  text "3.5" at 12360.84,6657 h60
  text "7" at 9511.58,6537 h60
  text "Bottom Overlay" at 9921.49,6537 h60
M13 Component Bodies Top:
  text ".Layer_Name" at 378,-1101.49 h60
M14 Component Bodies Bottom:
  text ".Layer_Name" at 378,-1101.49 h60
M15 Courtyards Top:
  text ".Layer_Name" at 378,-1101.49 h60
M16 Courtyards Bottom:
  text ".Layer_Name" at 378,-1101.49 h60
Drill Drawing:
  lines w1: 5458.13,3015.91 5478.9,2995.14 5499.67,3015.91 5478.9,3036.68 5458.13,3015.91
  lines w12: 5401,2957.76 7430.11,2957.76 ; 5401,3082.38 7430.11,3082.38 ; 5749.13,2833.13 5749.13,3207 ; 6091.32,2833.13 6091.32,3207 ; 6738.06,2833.13 6738.06,3207 ; 7007.38,2833.13 7007.38,3207 ; 5401,2833.13 7430.11,2833.13 7430.11,3207 5401,3207 5401,2833.13
  text "Symbol" at 5475.77,3119.76 h72
  text "Quantity" at 5786.52,3119.76 h72
  text "Finished Hole Size" at 6128.7,3119.76 h72
  text "Plated" at 6775.45,3119.76 h72
  text "Hole Type" at 7044.77,3119.76 h72
  text "18" at 5786.52,2995.14 h60
  text "15.00mil (0.381mm)" at 6128.7,2995.14 h60
  text "PTH" at 6775.45,2995.14 h60
  text "Round" at 7044.77,2995.14 h60
  text "18 Total" at 5786.52,2870.52 h60
  text ".Layer_Name" at 378,-1101.49 h60

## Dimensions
1501,0 to 1501,1000 on M2 Board Dimensions
1,1001 to 1501,1000 on M2 Board Dimensions
-199,-643 to 801,-643 on M2 Board Dimensions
